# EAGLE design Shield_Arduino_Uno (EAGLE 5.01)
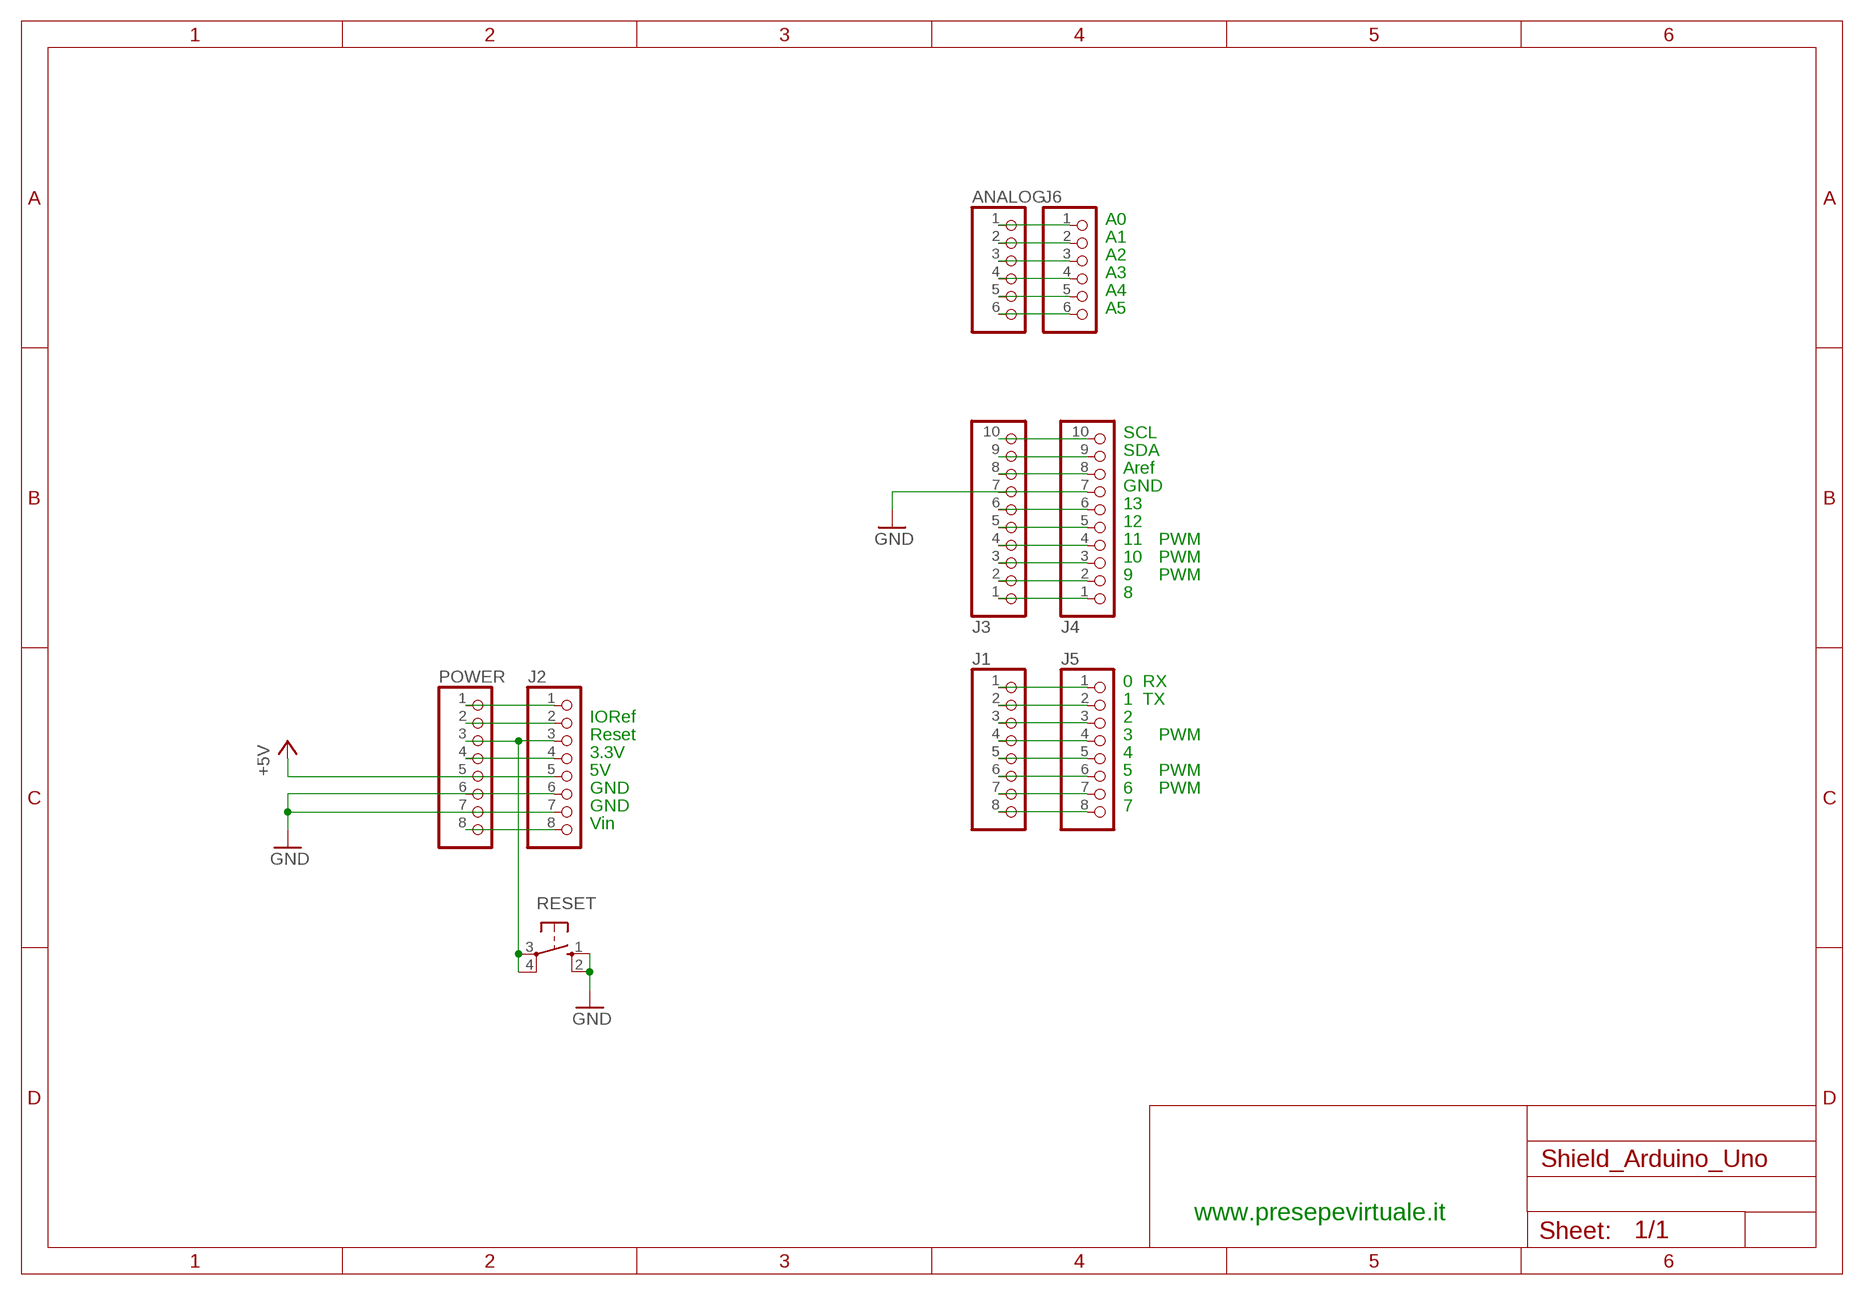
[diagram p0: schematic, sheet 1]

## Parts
ANALOG  PINHD-1X6  [1X06]
J1  PINHD-1X8TH  [1X08-TH]
J2  PINHD-1X8TH  [1X08-TH]
J3  PINHD-1X10TH  [1X10-TH]
J4  PINHD-1X10TH  [1X10-TH]
J5  PINHD-1X8TH  [1X08-TH]
J6  PINHD-1X6  [1X06]
POWER  PINHD-1X8TH  [1X08-TH]
RESET  10-XX  [B3F-10XX]

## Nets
+5V: J2.5 POWER.5
+9V: J2.8 POWER.8
GND: J2.7 J3.7 J4.7 POWER.7 RESET.1(S) RESET.2(S1)
N$1: J3.5 J4.5
N$2: J3.1 J4.1
N$3: J3.6 J4.6
N$5: J3.4 J4.4
N$6: J3.2 J4.2
N$7: J3.3 J4.3
N$8: J1.1 J5.1
N$9: J1.2 J5.2
N$10: J1.3 J5.3
N$11: J1.4 J5.4
N$12: J1.5 J5.5
N$13: J1.6 J5.6
N$14: J1.7 J5.7
N$15: J1.8 J5.8
N$18: ANALOG.1 J6.1
N$19: ANALOG.2 J6.2
N$20: ANALOG.3 J6.3
N$21: ANALOG.4 J6.4
N$22: ANALOG.5 J6.5
N$23: ANALOG.6 J6.6
N$25: J2.6 POWER.6
N$31: J2.2 POWER.2
N$32: J2.1 POWER.1
N$141: J3.9 J4.9
N$142: J3.10 J4.10
N$222: J3.8 J4.8
N$223: J2.4 POWER.4
RESET: J2.3 POWER.3 RESET.3(P) RESET.4(P1)

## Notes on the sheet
- A0
- A1
- A2
- A3
- A4
- A5
- SCL
- SDA
- Aref
- GND
- 13
- 12
- 11 | PWM
- 10 | PWM
- 9 | PWM
- 8
- 0  RX
- 1  TX
- IORef | 2
- Reset | 3 | PWM
- 3.3V | 4
- 5V | 5 | PWM
- GND | 6 | PWM
- GND | 7
- Vin
- www.presepevirtuale.it

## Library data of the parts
ANALOG J6 = pinhead:PINHD-1X6: PIN HEADER
J1 J2 J5 POWER = SmartPrj:PINHD-1X8: PIN HEADER
J3 J4 = SmartPrj:PINHD-1X10: PIN HEADER
RESET = switch-omron:10-XX: OMRON SWITCH

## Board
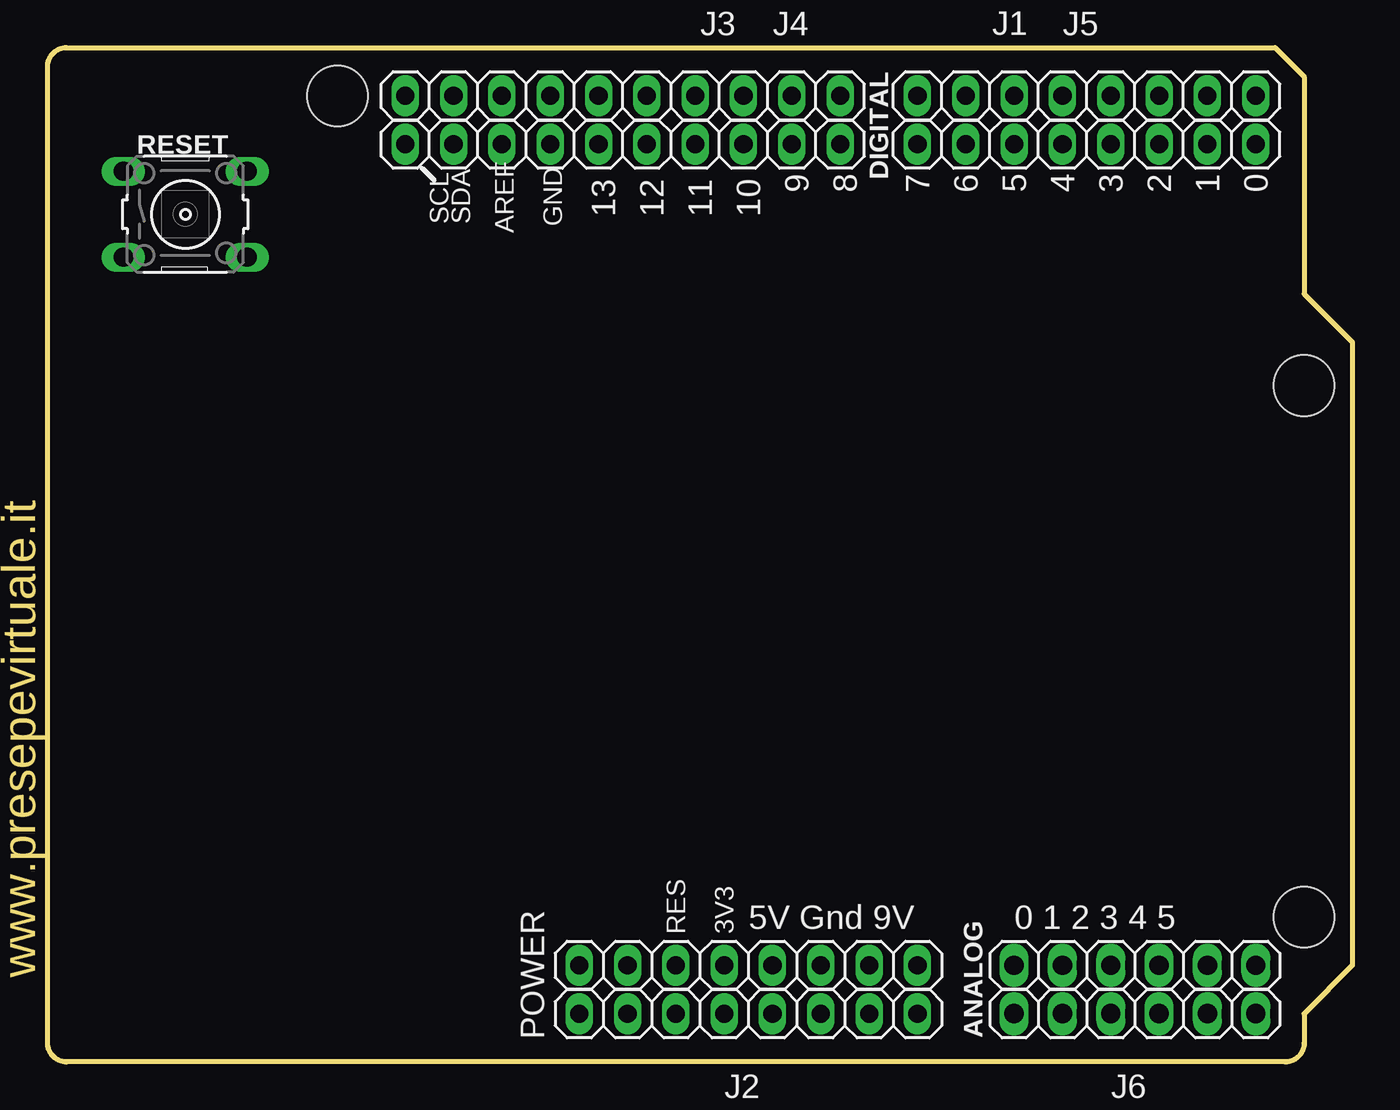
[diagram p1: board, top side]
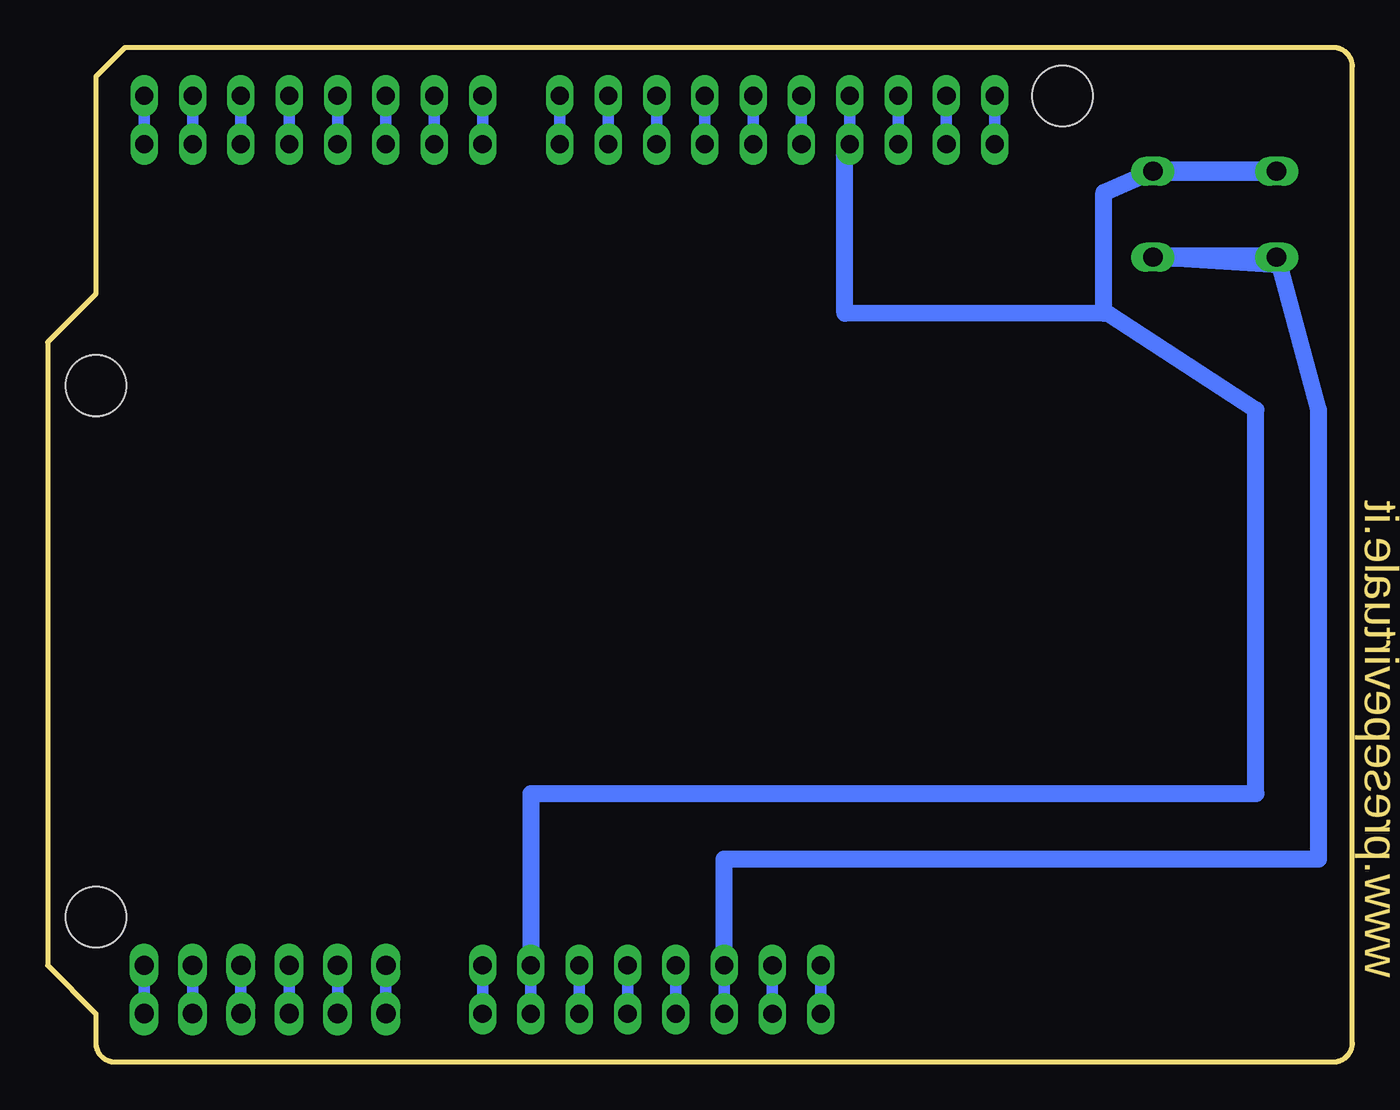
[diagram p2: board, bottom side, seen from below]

Size 68.58 x 53.34 mm. Coordinates in mm from the lower left corner, seen from the top.
Outline: 64.52,53.34 66.04,51.82 66.04,40.39 68.58,37.85 68.58,5.08 66.04,2.54 66.04,1 arc-90 65.04,0 1,0 arc-90 0,1 0,52.34 arc-90 1,53.34 64.52,53.34
Copper layers (1*16): Top 0.035mm / dielectric 1.5mm / Bottom 0.035mm
Design rules "default *": minimum track width 35mil, minimum drill 24mil, track to track 35mil, track to pad 35mil, pad to pad 35mil, via to via 35mil, smd to smd 8mil, copper to edge 40mil, drill to drill 8mil, minimum pad ring 10mil, minimum via ring 8mil, stop-mask expansion 2mil, vias tented up to drill 0mil, thermal gap 10mil
Holes 3.2 mm at 15.24,50.8 66.04,7.62 66.04,35.56

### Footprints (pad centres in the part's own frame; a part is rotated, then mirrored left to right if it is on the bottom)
1X06 = drill 1.016 long: 1 -6.35,0; 2 -3.81,0; 3 -1.27,0; 4 1.27,0; 5 3.81,0; 6 6.35,0
1X08-TH = drill 0.95 pad 1.422 long: 1 -8.89,0; 2 -6.35,0; 3 -3.81,0; 4 -1.27,0; 5 1.27,0; 6 3.81,0; 7 6.35,0; 8 8.89,0
1X10-TH = drill 0.95 pad 1.422 long: 1 -11.43,0; 2 -8.89,0; 3 -6.35,0; 4 -3.81,0; 5 -1.27,0; 6 1.27,0; 7 3.81,0; 8 6.35,0; 9 8.89,0; 10 11.43,0
B3F-10XX = drill 1.016 long: 1 -3.251,2.261; 2 3.251,2.261; 3 -3.251,-2.261; 4 3.251,-2.261

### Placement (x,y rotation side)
ANALOG  57.15,2.54 0 top
J1  54.61,50.8 180 top
J2  36.83,2.54 0 top
J3  30.23,50.8 180 top
J4  30.23,48.26 180 top
J5  54.61,48.26 180 top
J6  57.15,5.08 0 top
POWER  36.83,5.08 0 top
RESET  7.24,44.58 0 top

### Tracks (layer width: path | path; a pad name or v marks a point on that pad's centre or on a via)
+5V
  Bottom 0.61: J2.5 POWER.5
+9V
  Bottom 0.61: J2.8 POWER.8
GND
  Bottom 0.61: J4.7 J3.7 | J2.7 POWER.7
  Bottom 0.889: 12.86,39.36 5.08,34.29 5.08,14.1 43.18,14.1 POWER.7 | RESET.2 13.07,45.72 13.07,39.37 12.86,39.36 | 12.86,39.36 26.67,39.37 26.67,48.26 J4.7
  Bottom 1.016: RESET.1 RESET.2
N$1
  Bottom 0.61: J4.5 J3.5
N$2
  Bottom 0.61: J4.1 J3.1
N$3
  Bottom 0.61: J4.6 J3.6
N$5
  Bottom 0.61: J4.4 J3.4
N$6
  Bottom 0.61: J4.2 J3.2
N$7
  Bottom 0.61: J4.3 J3.3
N$8
  Bottom 0.61: J5.1 J1.1
N$9
  Bottom 0.61: J5.2 J1.2
N$10
  Bottom 0.61: J5.3 J1.3
N$11
  Bottom 0.61: J5.4 J1.4
N$12
  Bottom 0.61: J5.5 J1.5
N$13
  Bottom 0.61: J5.6 J1.6
N$14
  Bottom 0.61: J5.7 J1.7
N$15
  Bottom 0.61: J5.8 J1.8
N$18
  Bottom 0.61: ANALOG.1 J6.1
N$19
  Bottom 0.61: ANALOG.2 J6.2
N$20
  Bottom 0.61: ANALOG.3 J6.3
N$21
  Bottom 0.61: ANALOG.4 J6.4
N$22
  Bottom 0.61: ANALOG.5 J6.5
N$23
  Bottom 0.61: ANALOG.6 J6.6
N$25
  Bottom 0.61: J2.6 POWER.6
N$31
  Bottom 0.61: J2.2 POWER.2
N$32
  Bottom 0.61: J2.1 POWER.1
N$141
  Bottom 0.61: J4.9 J3.9
N$142
  Bottom 0.61: J4.10 J3.10
N$222
  Bottom 0.61: J4.8 J3.8
N$223
  Bottom 0.61: J2.4 POWER.4
RESET
  Bottom 0.61: J2.3 POWER.3
  Bottom 0.889: POWER.3 33.02,10.67 1.78,10.67 1.78,34.29 3.81,41.91 RESET.4
  Bottom 1.016: RESET.4 RESET.3

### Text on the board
Dimension: www.presepevirtuale.it
tPlace: 9 | 8 | 7 | 6 | 5 | 4 | 3 | 2 | 1 | 0 | 13 | 12 | 11 | 10 | Arduino UNO Shield
tNames: DIGITAL | AREF | SCL | SDA | GND | RES | 3V3 | 5V Gnd 9V | 0 1 2 3 4 5
bStop: DIGITAL | SDA | AREF | SCL | GND | 13 | 12 | 11 | 9 | 8 | 7 | 6 | 5 | 4 | 3 | 2 | 1 | 0 | 10 | 14 | 8 | 1 | 7 | 1 | 2 | 3 | 4 | +5V | GND | . | 5 | 6 | IOREF | RST | 3.3V | 5V | GND | GND | VIN | ANALOG | 0 | 1 | 2 | 3 | 4 | 5
Reference: USB | ETH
